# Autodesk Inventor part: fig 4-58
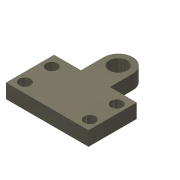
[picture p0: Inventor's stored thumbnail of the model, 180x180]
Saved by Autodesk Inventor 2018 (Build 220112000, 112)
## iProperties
Created: 2004-05
Part Number: fig 4-58
Document SubType Name: Modeling
Designer: CADCIM Technologies
Manufacturer: Standard
Standards Organization: Custom
Density: 1 g/cm^3
Material: Generic
Appearance: Metal-Titanium (Polished)
Author: CADCIM Technologies
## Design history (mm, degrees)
sketch "Sketch1"
  geometry: L1 (39.729, 55.62)-(39.729, 42.054); L2 (39.729, 42.054)-(23.837, 42.054); L3 (23.837, 42.054)-(23.837, 13.516); L4 (23.837, 13.516)-(72.804, 13.516); L5 (72.804, 13.516)-(72.804, 42.054); L6 (72.804, 42.054)-(56.912, 42.054); L7 (56.912, 42.054)-(56.912, 55.62); C1 r 3.354 at (29.212, 35.336); C2 r 3.354 at (29.212, 19.383); C3 r 3.354 at (67.7, 35.336); C4 r 3.354 at (67.7, 19.383); C5 r 5.297 at (48.32, 55.62); A1 r 8.592 centre (48.32, 55.62) between (56.912, 55.62) and (39.729, 55.62)
  constraints: 14 end point, 6 centre point, 4 parallel, 2 equal length, 2 horizontal alignment, 2 point on circle, 2 tangent, 2 vertical alignment, 1 coincident, 1 collinear, 1 perpendicular, 1 vertical
extrude "Extrusion1" new body sketch "Sketch1" distance "d0" = 8.5; taper "d1" = 0 deg
body "Solid1"
